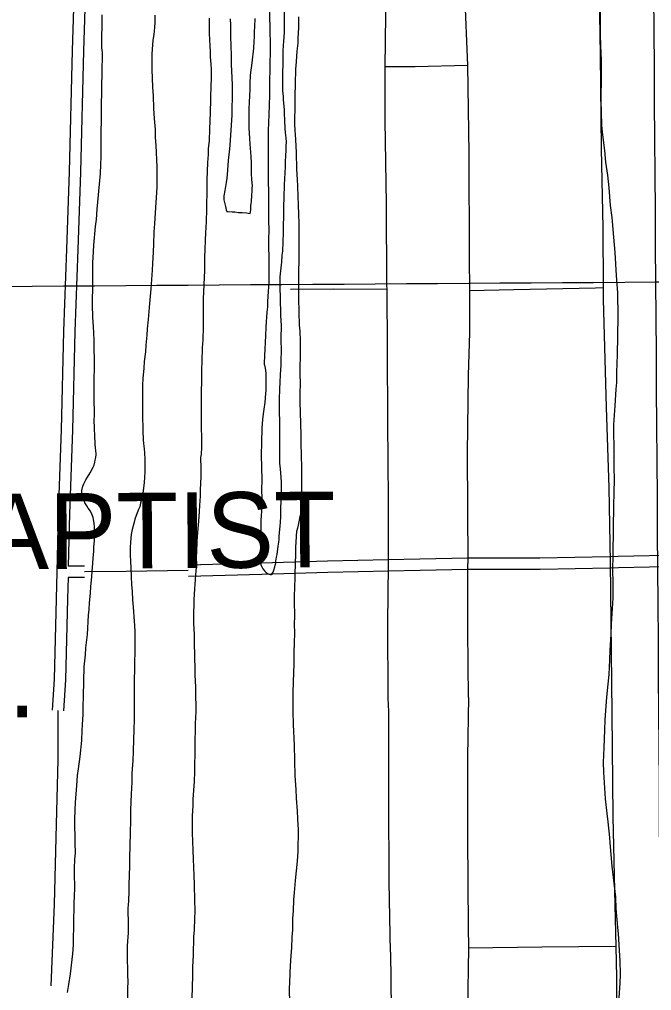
# Model space of a CAD drawing. Extents: x 3508733 to 3546731, y 546897 to 572481.
# Drawn here: x 3532290 to 3533961, y 556625 to 559192 of the extents above; entities that cross this region are included whole.
import ezdxf

# ---------------------------------------------------------------- set-up
doc = ezdxf.new("R2010")
doc.units = 0
for name, color, linetype in [('V-DTCH-CNTR', 7, 'Continuous'), ('V-GRID-MAJR', 7, 'Continuous'), ('V-ROAD-CNTR', 7, 'Continuous'), ('V-SITE-VEGE', 7, 'Continuous'), ('V-TOPO-GNAM-IDEN', 7, 'Continuous')]:
    doc.layers.add(name, color=color, linetype=linetype)

msp = doc.modelspace()

# ---------------------------------------------------------------- linework, layer by layer
at = {"layer": 'V-DTCH-CNTR'}
for points in [[(3533784.645, 560922.076), (3533790, 560756.678), (3533789.579, 560542.088), (3533793.89, 560331.554), (3533803.566, 560129.76), (3533804.558, 560115.881), (3533806.9990000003, 559952.27), (3533810.7490000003, 559744.087), (3533820.378, 559480.145), (3533821.472, 559298.958), (3533822.15, 559257.327), (3533824.722, 559099.575), (3533827.469, 558850.36), (3533831.79, 558640.9990000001), (3533832.6380000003, 558483.279), (3533832.804, 558452.192), (3533841.049, 558167.156), (3533847.68, 557954.254), (3533850.93, 557757.789), (3533853.8000000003, 557520.887), (3533855.661, 557357.868)], [(3533264.545, 557397.777), (3533264.224, 557597.527), (3533265.25, 557749.997), (3533265.235, 557922.133), (3533263.787, 558126.593), (3533262.819, 558320.475), (3533261.694, 558478.009), (3533261.606, 558490.273), (3533260.261, 558704.721), (3533256.617, 558924.479), (3533256.673, 559066.721), (3533259.454, 559273.074)], [(3533466.306, 559262.701), (3533474.1950000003, 559070.385), (3533477.83, 558838.67), (3533479.122, 558561.914), (3533479.274, 558475.7220000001), (3533479.466, 558364.904), (3533475.966, 558251.193), (3533473.296, 558046.008), (3533475.548, 557754.002)], [(3533474.1950000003, 559070.385), (3533335.789, 559067.1), (3533256.673, 559066.721)], [(3533479.274, 558475.7220000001), (3533596.5670000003, 558478.634), (3533812.373, 558482.306), (3533832.6380000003, 558483.279)], [(3533261.694, 558478.009), (3533120.399, 558478.857), (3533006.647, 558478.253)], [(3533476.64, 557400.327), (3533475.487, 557576.001), (3533475.548, 557754.002)], [(3533271.109, 556727.0700000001), (3533267.187, 556912.719), (3533266.681, 557132.856), (3533266.292, 557362.922), (3533264.545, 557397.777)], [(3533476.64, 557400.327), (3533474.199, 557243.336), (3533474.367, 557031.5970000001), (3533476.472, 556791.025), (3533477.1950000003, 556740.834)], [(3533855.661, 557357.868), (3533858.703, 557085.447), (3533863.8000000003, 556851.5430000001), (3533866.0840000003, 556741.647), (3533867.769, 556660.407), (3533870.198, 556391.23), (3533876.006, 556134.323), (3533881.515, 555879.687), (3533885.46, 555629.604), (3533889.8200000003, 555416.1140000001), (3533891.899, 555258.035)], [(3533477.1950000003, 556740.834), (3533477.1520000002, 556737.951), (3533474.653, 556575.102), (3533475.54, 556369.507), (3533474.092, 556129.623), (3533474.164, 555880.979), (3533474.881, 555746.987), (3533475.403, 555649.48), (3533479.204, 555359.028), (3533477.623, 555107.491), (3533479.21, 554793.106), (3533479.892, 554711.191)], [(3533866.0840000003, 556741.647), (3533670.903, 556739.8), (3533477.1520000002, 556737.951)], [(3533271.109, 556727.0700000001), (3533272.844, 556576.841), (3533272.166, 556404.194), (3533273.485, 556198.723), (3533274.078, 555948.584), (3533274.66, 555735.133)]]:
    msp.add_lwpolyline(points, dxfattribs=at)
at = {"layer": 'V-GRID-MAJR'}
for points in [[(3534014.4590000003, 552440.283), (3533972.165, 558498.1140000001), (3533929.85, 564559.029), (3533887.535, 570619.961), (3533887.514, 570623.028)], [(3512877.5640000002, 558356.976), (3518151.221, 558391.11), (3523424.875, 558426.011), (3528698.522, 558461.679), (3533972.165, 558498.1140000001), (3539245.802, 558535.316), (3544519.434, 558573.285), (3544519.435, 558573.285)]]:
    msp.add_spline(points, degree=3, dxfattribs=at)
at = {"layer": 'V-ROAD-CNTR'}
for p, q in [((3532462.4615447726, 557746.9739999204), (3532419.5511528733, 557746.9784190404)), ((3532462.4584552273, 557716.9740000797), (3532418.854686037, 557716.978490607))]:
    msp.add_line(p, q, dxfattribs=at)
for points in [[(3532465.2551178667, 560452.7004527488), (3532462.1440149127, 560319.9550598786), (3532456.8562898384, 560088.5490914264), (3532451.9148342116, 559891.2238296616), (3532445.1252728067, 559627.5666942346), (3532437.4320006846, 559390.8465513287), (3532435.104791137, 559277.4733429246), (3532429.8762249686, 559109.5503925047), (3532421.3386289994, 558789.4695399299), (3532414.56358583, 558585.1505532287), (3532407.0731313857, 558368.3715198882), (3532400.8995116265, 558107.6035808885), (3532392.774383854, 557886.1990991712), (3532389.2030406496, 557732.3281424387), (3532387.5506467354, 557661.1702426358), (3532381.8670998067, 557448.2484558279), (3532376.9424034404, 557366.8882848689)], [(3532495.2468821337, 560451.9975472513), (3532492.1359850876, 560319.2609401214), (3532486.847710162, 560087.8309085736), (3532481.9051657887, 559890.4621703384), (3532475.1127271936, 559626.6933057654), (3532467.4219993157, 559390.0514486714), (3532465.0952088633, 559276.6986570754), (3532459.8637750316, 559108.6836074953), (3532451.325371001, 558788.5724600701), (3532444.5464141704, 558584.1354467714), (3532437.0608686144, 558367.4984801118), (3532430.886488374, 558106.6984191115), (3532422.761616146, 557885.3009008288), (3532419.5480620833, 557746.8452526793)], [(3532735.8316419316, 557750.6496517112), (3532930.3391030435, 557756.3103741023), (3533104.349631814, 557761.5961823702), (3533264.932569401, 557764.9936408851), (3533348.3052498, 557766.7591847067), (3533474.7809253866, 557769.0017144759), (3533665.71604801, 557769.41170615), (3533850.6564458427, 557772.7865053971), (3533872.3767595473, 557773.1825083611), (3534036.993979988, 557777.387531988), (3534083.5773681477, 557777.7445619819), (3534195.506095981, 557778.5975006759), (3534437.487886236, 557784.9470577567), (3534687.262196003, 557791.2227941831), (3534940.667937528, 557796.8809143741), (3535048.7228697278, 557797.581533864)], [(3532736.7043580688, 557720.6623482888), (3532931.2308969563, 557726.3236258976), (3533105.1223681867, 557731.6058176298), (3533265.567430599, 557735.0003591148), (3533348.8887502, 557736.7648152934), (3533475.0790746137, 557739.0022855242), (3533666.02195199, 557739.41229385), (3533851.203554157, 557742.7914946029), (3533873.033240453, 557743.1894916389), (3534037.492020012, 557747.3904680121), (3534083.806631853, 557747.7454380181), (3534196.013904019, 557748.6004993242), (3534438.2581137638, 557754.9569422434), (3534687.973803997, 557761.231205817), (3534941.1000624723, 557766.883085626), (3535049.160988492, 557767.5837439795)], [(3532736.268, 557735.656), (3532572.333, 557733.209), (3532462.46, 557731.974)], [(3532418.8657245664, 557717.4538485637), (3532417.541353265, 557660.4217573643), (3532411.8429001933, 557446.941544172), (3532406.8875965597, 557365.075715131)], [(3532391.915, 557365.982), (3532392.0500000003, 557236.055), (3532387.165, 557064.066), (3532381.845, 556853.526), (3532373.54, 556637.5430000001)]]:
    msp.add_lwpolyline(points, dxfattribs=at)
at = {"layer": 'V-SITE-VEGE'}
for points in [[(3532995.127, 558879.389), (3532993.365, 558893.17), (3532992.515, 558902.781), (3532992.29, 558911.104), (3532991.737, 558918.792), (3532991.5470000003, 558929.995), (3532991.008, 558938.963), (3532990.539, 558954.01), (3532988.272, 558979.319), (3532987.739, 558988.926), (3532986.291, 559002.383), (3532986.0700000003, 559011.026), (3532986.582, 559055.826), (3532987.057, 559069.261), (3532987.526, 559110.221), (3532989.4020000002, 559134.52), (3532989.8370000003, 559144.435), (3532990.33, 559159.473), (3532991.082, 559225.39)], [(3532489.5530000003, 557834.341), (3532489.092, 557850.029), (3532487.937, 557860.924), (3532484.9080000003, 557876), (3532481.488, 557884.679), (3532478.056, 557892.4), (3532472.063, 557900.15), (3532468.612, 557906.269), (3532463.58, 557914.009), (3532462.028, 557917.867), (3532459.208, 557923.337), (3532457.6350000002, 557925.9180000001), (3532455.7630000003, 557930.1), (3532454.907, 557939.0700000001), (3532455.634, 557946.742), (3532458.0100000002, 557958.557), (3532460.963, 557964.924), (3532465.88, 557975.109), (3532476.97, 557993.5430000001), (3532485.467, 558008.806), (3532487.45, 558014.225), (3532489.453, 558021.563), (3532490.794, 558026.9890000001), (3532492.162, 558034.652), (3532492.887, 558042.007), (3532492.066, 558054.176), (3532491.466, 558057.704), (3532490.344, 558071.477), (3532490.112, 558079.161), (3532489.52, 558083.649), (3532488.642, 558118.542), (3532488.097, 558126.867), (3532488.382, 558151.831), (3532488.1750000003, 558189.596), (3532487.577, 558221.284), (3532488.378, 558291.363), (3532488.089, 558322.091), (3532488.0270000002, 558344.814), (3532486.194, 558380.357), (3532484.546, 558404.058), (3532483.657, 558438.313), (3532484.29, 558493.67), (3532484.22, 558515.754), (3532484.62, 558550.633), (3532485.068, 558561.83), (3532487.372, 558595.407), (3532491.771, 558644.321), (3532493.5840000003, 558662.862), (3532495.4990000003, 558690.362), (3532497.6350000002, 558709.22), (3532499.887, 558738.318), (3532501.7, 558756.857), (3532504.901, 558784.986), (3532506.382, 558830.4130000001), (3532505.96, 558849.621), (3532507.346, 558970.897), (3532508.276, 558996.17), (3532509.11, 559069.128), (3532509.595, 559083.523), (3532510.017, 559092.479), (3532510.06, 559096.319), (3532509.832, 559104.323), (3532508.37, 559116.5), (3532509.37, 559203.857)], [(3532647.941, 559203.554), (3532647.696, 559182.116), (3532647.2660000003, 559172.519), (3532646.487, 559160.366), (3532645.123, 559153.341), (3532642.6920000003, 559136.407), (3532642.238, 559124.571), (3532640.366, 559100.911), (3532639.899, 559059.951), (3532641.605, 559013.207), (3532643.901, 558990.138), (3532644.794, 558956.203)], [(3532950.988, 559217.53), (3532951.852, 559153.192), (3532952.631, 559137.181), (3532953.11, 559123.095), (3532952.362, 559057.817), (3532951.418, 559031.264), (3532950.9960000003, 558994.144), (3532950.3200000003, 558963.111), (3532949.452, 558943.278), (3532948.512, 558917.045), (3532947.687, 558900.733), (3532947.4220000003, 558877.6950000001), (3532947.883, 558862.007), (3532947.9450000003, 558839.285), (3532947.773, 558824.2440000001), (3532947.826, 558800.881), (3532947.468, 558769.522), (3532948.616, 558730.145), (3532948.745, 558713.503), (3532948.41, 558684.063), (3532948.4960000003, 558663.579), (3532949.102, 558632.529), (3532948.881, 558613.331), (3532949.659, 558541.313), (3532949.163, 558498.115), (3532947.13, 558460.052), (3532946.02, 558446.9450000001), (3532945.534, 558432.55), (3532944.414, 558418.48), (3532941.727, 558379.468), (3532940.49, 558355.158), (3532939.353, 558339.81), (3532938.477, 558319.019), (3532937.686, 558305.906), (3532937.406, 558281.2660000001), (3532937.688, 558278.063), (3532939.519, 558270.361)], [(3533027.954, 559198.612), (3533027.616, 559169.172), (3533026.838, 559157.022), (3533026.328, 559140.386), (3533025.879, 559129.189), (3533023.723, 559108.41), (3533022.605, 559094.662), (3533021.153, 559079.638), (3533019.973, 559060.448), (3533019.827, 559047.648), (3533019.361, 559034.852), (3533019.1410000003, 559015.654), (3533018.267, 558995.183), (3533018.435, 558981.737), (3533017.964, 558968.622), (3533017.741, 558949.103), (3533017.259, 558935.027), (3533017.341, 558914.223), (3533017.81, 558899.176), (3533019.772, 558874.832), (3533020.5300000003, 558857.221), (3533021.613, 558839.928), (3533022.715, 558796.389), (3533024.325, 558769.169), (3533025.079, 558751.2390000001), (3533025.718, 558723.069), (3533026.463, 558704.178), (3533027.4050000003, 558674.724), (3533028.458, 558654.871), (3533028.7630000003, 558625.422), (3533028.523, 558604.623), (3533028.484, 558573.262), (3533027.737, 558507.662), (3533027.682, 558475.019), (3533028.0870000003, 558454.533), (3533029.842, 558384.106), (3533030.94, 558368.091), (3533032.24, 558341.834), (3533032.349, 558323.2710000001), (3533032.034, 558295.752), (3533031.509, 558278.155), (3533031.532, 558251.912), (3533031.964, 558233.667), (3533031.577, 558199.748), (3533031.683, 558181.185), (3533032.955, 558124.525), (3533033.875, 558092.83), (3533033.955, 558072.026), (3533035.187, 558039.688), (3533035.466, 558008.006), (3533035.296, 557993.283), (3533035.982, 557969.274), (3533035.796, 557952.953), (3533036.5100000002, 557931.503), (3533036.6720000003, 557917.74), (3533036.218, 557905.905), (3533035.108, 557892.795), (3533035.069, 557889.275), (3533033.1010000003, 557885.138), (3533031.427, 557878.756), (3533029.713, 557868.854)], [(3533876.0160000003, 556731.063), (3533873.004, 556776.424), (3533871.419, 556792.337), (3533867.282, 556842.421), (3533865.858, 556872.459), (3533856.788, 556954.387), (3533851.602, 557015.6680000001), (3533849.9990000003, 557029.8150000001), (3533846.349, 557071.062), (3533843.072, 557093.469), (3533839.39, 557131.775), (3533836.7770000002, 557160.65), (3533834.313, 557202.474), (3533834.018, 557228.377), (3533835.044, 557266.63), (3533836.498, 557290.7490000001), (3533837.362, 557314.8740000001), (3533837.659, 557340.7710000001), (3533840.43, 557377.238), (3533842.464, 557400.761), (3533846.394, 557435.446), (3533848.448, 557460.735), (3533850.6580000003, 557499.5650000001), (3533851.543, 557525.454), (3533853.773, 557566.047), (3533854.684, 557594.291), (3533857.509, 557635.466), (3533859.012, 557663.704), (3533859.495, 557706.083), (3533858.647, 557734.936), (3533859.145, 557778.4940000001), (3533860.646, 557909.7490000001), (3533862.145, 557937.9890000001), (3533862.616, 557979.188), (3533861.73, 558004.512), (3533861.551, 558040.4230000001), (3533860.708, 558121.08), (3533864.812, 558171.069), (3533867.075, 558214.606), (3533869.049, 558232.831), (3533869.358, 558259.906), (3533871.06, 558305.803), (3533872.213, 558406.452), (3533871.755, 558469.4450000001), (3533868.1520000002, 558514.814), (3533864.142, 558576.08), (3533861.068, 558616.145), (3533856.37, 558668.588), (3533852.614, 558700.42), (3533849.026, 558746.965), (3533845.288, 558780.562), (3533839.793, 558814.768), (3533837.201, 558845.408), (3533831.786, 558886.678), (3533829.713, 558911.426), (3533828.357, 558947.35), (3533827.503, 558975.616), (3533828.304, 559045.658), (3533828.153, 559083.922), (3533826.832, 559122.789), (3533825.382, 559150.4720000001), (3533826.1890000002, 559221.104)], [(3532784.59, 558659.372), (3532785.233, 558687.528), (3532785.444, 558706.089), (3532786.3740000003, 558731.359), (3532786.788, 558767.519), (3532788.594, 558813.582), (3532789.798, 558835.011), (3532790.288, 558849.727), (3532792.147, 558872.428), (3532793.767, 558902.1730000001), (3532795.232, 558946.321), (3532795.311, 558953.36), (3532795.858, 558973.1950000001), (3532796.325, 558985.991), (3532796.677, 559016.711), (3532797.529, 559035.262), (3532797.804, 559059.262), (3532797.3310000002, 559073.67), (3532795.631, 559093.21), (3532795.133, 559105.701), (3532794.066, 559124.272), (3532793.2430000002, 559136.443), (3532792.846, 559157.571), (3532792.383, 559172.937), (3532792.313, 559195.02)], [(3532847.3370000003, 559193.112), (3532848.115, 559176.781), (3532847.98, 559165.261), (3532848.453, 559150.534), (3532848.346, 559141.254), (3532848.828, 559127.487), (3532848.7090000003, 559117.247), (3532849.504, 559102.5160000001), (3532850.007, 559090.669), (3532850.1040000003, 559071.147), (3532850.91, 559057.696), (3532851.625, 559036.245), (3532852.725, 559020.551), (3532852.85, 559003.268), (3532852.643, 558985.348), (3532852.002, 558957.194), (3532851.47, 558938.637), (3532849.569, 558912.417), (3532846.88, 558873.083), (3532846.403, 558859.326), (3532844.912, 558840.782), (3532843.161, 558827.681), (3532841.33, 558807.539), (3532840.197, 558792.51), (3532838.051, 558772.692), (3532836.636, 558760.8690000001), (3532834.592, 558750.01), (3532832.88, 558740.108), (3532830.7970000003, 558726.051), (3532830.4020000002, 558719.335), (3532830.3510000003, 558714.854), (3532830.949, 558711.328), (3532834.633, 558697.846), (3532836.773, 558688.859), (3532838.3170000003, 558684.04), (3532841.518, 558684.005), (3532852.072, 558683.2440000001), (3532859.75, 558683.155), (3532869.338, 558682.086), (3532871.898, 558682.058), (3532879.255, 558681.652), (3532890.1240000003, 558680.569), (3532894.92, 558680.194), (3532900.349, 558679.172), (3532901.418, 558688.761), (3532901.525, 558698.04), (3532902.901, 558706.345), (3532903.579, 558709.857), (3532903.948, 558714.015), (3532904.056, 558723.6140000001), (3532904.447, 558729.6900000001), (3532905.166, 558736.723), (3532905.512, 558738.959), (3532905.606, 558747.278), (3532906.2970000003, 558751.43), (3532904.589, 558770.013), (3532903.788, 558784.103), (3532903.681, 558802.666), (3532903.804, 558813.545), (3532903.026, 558829.237), (3532902.196, 558840.767), (3532900.198, 558861.911), (3532899.102, 558877.926), (3532897.482, 558904.188), (3532897.361, 558921.79), (3532897.728, 558953.79), (3532898.293, 558975.227), (3532899.088, 558988.658), (3532899.6410000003, 559009.134), (3532899.794, 559022.575), (3532901.33, 559044.957), (3532904.9, 559077.242), (3532909.506, 559116.232), (3532910.663, 559133.5), (3532911.126, 559145.977), (3532911.916, 559159.088), (3532912.074, 559172.849), (3532912.963, 559194.6)], [(3532644.794, 558956.203), (3532646.092, 558929.948), (3532648.64, 558900.794), (3532649.369, 558880.6240000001), (3532650.725, 558859.167), (3532653.276, 558802.49), (3532653.661, 558780.085), (3532653.299, 558748.405), (3532649.328, 558681.245), (3532647.071, 558651.508), (3532645.877, 558631.0380000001), (3532644.869, 558599.046), (3532643.661, 558577.2980000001), (3532642.3540000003, 558546.91), (3532641.187, 558528.998), (3532637.429, 558480.08), (3532634.5330000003, 558450.669), (3532633.784, 558441.078), (3532630.1010000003, 558398.875), (3532628.219, 558374.254), (3532627.068, 558357.626), (3532624.523, 558330.77), (3532623.04, 558313.186), (3532620.191, 558287.937), (3532618.714, 558270.672), (3532616.1580000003, 558243.177), (3532615.6380000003, 558225.581), (3532615.1180000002, 558180.142), (3532615.661, 558171.495), (3532615.8140000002, 558157.094), (3532615.526, 558131.813), (3532616.052, 558121.887), (3532616.1750000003, 558104.604), (3532617.185, 558080.908), (3532618.0300000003, 558070.978), (3532619.79, 558056.877), (3532620.633, 558046.627), (3532621.715, 558029.331), (3532621.883, 558015.888), (3532621.651, 557995.73), (3532621.1920000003, 557983.573), (3532620.363, 557966.943), (3532616.535, 557940.104), (3532614.807, 557928.922), (3532610.467, 557913.2880000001), (3532608.116, 557903.713), (3532604.176, 557894.7980000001), (3532594.941, 557870.9), (3532592.258, 557860.052), (3532587.91, 557843.779), (3532585.52, 557830.686), (3532584.0130000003, 557810.859), (3532583.2060000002, 557796.148), (3532582.969, 557775.349), (3532583.444, 557760.939), (3532585.223, 557720.598), (3532586.559, 557697.539), (3532587.974, 557681.202), (3532589.295, 557656.8640000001), (3532589.85, 557649.497), (3532591.838, 557627.3910000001), (3532592.957, 557613.297), (3532594.614, 557590.236), (3532595.062, 557573.59), (3532595.386, 557545.743), (3532595.136, 557523.983), (3532594.093, 557488.7930000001), (3532593.454, 557432.792), (3532593.85, 557411.345), (3532593.85, 557383.501), (3532593.399, 557344.144), (3532592.717, 557312.468), (3532591.832, 557291.0380000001), (3532590.802, 557256.805), (3532589.571, 557233.137), (3532587.2630000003, 557199.242), (3532587.003, 557176.52), (3532585.682, 557144.851), (3532584.484, 557124.064), (3532584.23, 557101.985), (3532583.544, 557069.9890000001), (3532582.981, 557048.552), (3532582.446, 557001.833), (3532581.59, 556982.961), (3532581.259, 556953.843), (3532579.745, 556905.534), (3532579.544, 556887.936), (3532578.615, 556862.664), (3532577.84, 556850.83), (3532576.808, 556844.443), (3532576.694, 556834.522), (3532576.911, 556825.56), (3532577.4450000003, 556816.272), (3532577.339, 556806.993), (3532577.472, 556790.67), (3532577.322, 556777.547), (3532575.805, 556756.7660000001), (3532575.313, 556741.729), (3532575.059, 556719.65), (3532575.213, 556704.927), (3532575.9280000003, 556683.476)], [(3532939.519, 558270.361), (3532941.287, 558256.899), (3532941.696, 558236.732), (3532941.403, 558211.134), (3532940.9960000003, 558203.459), (3532938.485, 558179.804), (3532936.04, 558161.911), (3532934.625, 558150.086), (3532932.529, 558134.746), (3532931.307, 558111.718), (3532931.186, 558101.159), (3532930.039, 558084.851), (3532929.4080000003, 558029.813), (3532929.924, 558018.926), (3532930.094, 558005.802), (3532930.7290000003, 557977.31), (3532930.381, 557946.912), (3532930.49, 557928.349), (3532930.086, 557893.15), (3532929.289, 557879.397), (3532928.538, 557869.805), (3532928.36, 557854.125), (3532927.915, 557842.931), (3532927.291, 557788.532), (3532927.454, 557774.767), (3532928.282, 557763.2390000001), (3532928.466, 557751.393), (3532929.0810000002, 557749.147), (3532933.779, 557740.131), (3532937.877, 557734.645), (3532941.041, 557731.409), (3532946.116, 557727.51), (3532953.126, 557724.87), (3532956.651, 557725.148), (3532960.88, 557731.182), (3532962.86, 557736.599), (3532965.203, 557745.534), (3532966.534, 557749.9990000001), (3532967.556, 557755.428), (3532967.927, 557759.905), (3532969.969, 557770.442), (3532971.017, 557778.109), (3532974.468, 557800.152), (3532975.861, 557810.058), (3532976.267, 557817.415), (3532977.0100000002, 557826.3690000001), (3532977.4420000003, 557836.283), (3532979.23, 557852.585), (3532979.99, 557863.134), (3532980.799, 557877.849), (3532981.231, 557887.7660000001), (3532981.413, 557903.764), (3532982.181, 557914.957), (3532982.808, 557969.675), (3532980.006, 558004.5920000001), (3532978.575, 558019.329), (3532978.171, 558040.137), (3532978.714, 558087.495), (3532978.286, 558106.062), (3532978.415, 558117.26), (3532978.302, 558135.504), (3532977.8170000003, 558148.951), (3532977.665, 558163.674), (3532977.946, 558188.314), (3532978.566, 558214.5480000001), (3532979.427, 558233.74), (3532979.957, 558252.297), (3532981.5300000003, 558277.883), (3532982.3680000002, 558295.154), (3532982.5640000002, 558312.435), (3532982.034, 558349.884), (3532982.4020000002, 558382.204), (3532981.622, 558397.572), (3532981.427, 558408.777), (3532980.676, 558427.026), (3532980.5100000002, 558440.47), (3532979.8030000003, 558462.561), (3532979.0130000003, 558477.61), (3532979.302, 558502.89), (3532979.721, 558511.527), (3532982.963, 558543.1730000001), (3532983.367, 558550.531), (3532984.86, 558569.074), (3532985.943, 558579.942), (3532988.4280000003, 558629.201), (3532989.116, 558689.359), (3532988.862, 558695.122), (3532988.899, 558698.319), (3532990.109, 558720.39), (3532990.224, 558730.311), (3532990.725, 558746.306), (3532991.162, 558756.541), (3532991.9420000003, 558768.694), (3532992.485, 558788.21), (3532993.5840000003, 558800.358), (3532993.791, 558818.598), (3532994.5670000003, 558830.429), (3532995.086, 558847.706), (3532995.522, 558857.942), (3532995.632, 558867.541), (3532995.127, 558879.389)], [(3532746.379, 556604.556), (3532748.67, 556665.015), (3532748.932, 556687.736), (3532750.255, 556719.724), (3532751.441, 556767.395), (3532752.617, 556786.263), (3532753.913, 556815.693), (3532754.4560000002, 556835.208), (3532754.165, 556865.615), (3532752.6780000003, 556903.716), (3532751.714, 556931.2490000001), (3532750.9560000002, 556948.86), (3532750.616, 556975.105), (3532749.551, 556994), (3532748.273, 557022.178), (3532747.8310000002, 557039.465), (3532747.7630000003, 557061.547), (3532748.0700000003, 557088.429), (3532748.523, 557099.943), (3532749.33, 557114.656), (3532749.836, 557130.97), (3532752.615, 557177.984), (3532753.878, 557204.532), (3532755.322, 557330.927), (3532756.969, 557362.914), (3532757.1, 557374.434), (3532756.197, 557407.407), (3532756.438, 557428.526), (3532754.861, 557458.628), (3532754.7630000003, 557477.832), (3532753.788, 557504.726), (3532752.701, 557549.544), (3532752.586, 557567.466), (3532751.613, 557594.359), (3532751.171, 557611.6460000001), (3532751.701, 557658.045), (3532753.639, 557687.4670000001), (3532756.623, 557724.554), (3532757.794, 557743.103), (3532758.423, 557769.981), (3532759.252, 557786.613), (3532759.85, 557810.927), (3532761.304, 557826.272), (3532764.643, 557866.2390000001), (3532766.207, 557891.184), (3532766.713, 557907.498), (3532768.591, 557931.8), (3532769.091, 557947.155), (3532769.326, 557967.957), (3532770.438, 557981.384), (3532770.352, 558001.868), (3532770.49, 558014.027), (3532769.988, 558025.8740000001), (3532769.7630000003, 558034.198), (3532771.778, 558042.496), (3532772.636, 558061.688), (3532772.646, 558090.491), (3532771.589, 558110.025), (3532771.294, 558140.431), (3532771.219, 558161.554), (3532771.464, 558182.993), (3532771.481, 558212.437), (3532772.032, 558232.591), (3532772.73, 558265.867), (3532773.637, 558289.219), (3532774.035, 558323.779), (3532775.563, 558345.522), (3532776.9, 558378.47), (3532776.509, 558400.2390000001), (3532776.5500000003, 558431.921), (3532777.119, 558453.677), (3532780.214, 558528.21), (3532780.611, 558563.087), (3532783.294, 558629.944), (3532784.056, 558640.5), (3532784.59, 558659.372)], [(3533029.713, 557868.854), (3533028.011, 557859.9130000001), (3533024.984, 557847.145), (3533022.646, 557838.532), (3533021.562, 557827.6630000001), (3533020.3910000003, 557809.1140000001), (3533019.9560000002, 557799.198), (3533019.66, 557773.278), (3533019.1720000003, 557758.563), (3533019.051, 557748.004), (3533018.218, 557731.05), (3533017.751, 557718.255), (3533017.4250000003, 557689.775), (3533016.549, 557668.984), (3533016.372, 557653.6240000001), (3533016.911, 557616.813), (3533016.626, 557591.854), (3533017.0500000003, 557572.9670000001), (3533016.698, 557542.2490000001), (3533015.49, 557520.502), (3533015.113, 557487.541), (3533014.236, 557466.75), (3533012.985, 557413.318), (3533012.875, 557375.555), (3533012.741, 557364.037), (3533013.616, 557328.502), (3533016.19, 557273.746), (3533018.464, 557192.752), (3533020.294, 557156.888), (3533021.31, 557133.833), (3533023.811, 557100.522), (3533025.173, 557079.705), (3533026.443, 557050.568), (3533025.789, 556993.609), (3533023.889, 556967.384), (3533018.824, 556916.2390000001), (3533015.901, 556884.59), (3533014.718, 556865.08), (3533013.43, 556836.296), (3533012.236, 556815.826), (3533011.578, 556786.39), (3533010.394, 556766.881), (3533009.106, 556738.0920000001), (3533007.918, 556718.263), (3533005.369, 556691.09), (3533004.517, 556672.5380000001), (3533003.544, 556643.425), (3533003.437, 556634.1460000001), (3533003.865, 556587.736)], [(3532417.107, 556620.324), (3532420.865, 556641.084), (3532425.355, 556669.834), (3532431.716, 556722.2490000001), (3532433.268, 556746.233), (3532433.4560000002, 556762.551), (3532434.474, 556795.504), (3532435.22, 556860.782), (3532435.969, 556870.3740000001), (3532436.315, 556900.775), (3532436.711, 556907.171), (3532436.449, 556912.295), (3532435.586, 556920.944), (3532435.898, 556948.143), (3532436.4960000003, 556972.459), (3532438.281, 556988.761), (3532437.95, 557015.647), (3532437.188, 557032.938), (3532436.8540000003, 557059.825), (3532437.059, 557077.745), (3532437.9930000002, 557103.336), (3532438.8510000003, 557122.528), (3532441.603, 557167.302), (3532444.149, 557194.155), (3532446.269, 557211.411), (3532450.481, 557244.007), (3532454.805, 557286.202), (3532456.0640000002, 557312.431), (3532456.566, 557328.426), (3532458.794, 557355.283), (3532459.009, 557374.164), (3532459.6750000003, 557404.2390000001), (3532461.836, 557481.3420000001), (3532465.0670000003, 557512.349), (3532466.247, 557531.2170000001), (3532469.843, 557566.06), (3532472.9930000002, 557617.5480000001), (3532474.449, 557632.894), (3532475.9220000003, 557649.839), (3532477.8140000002, 557675.421), (3532479.2970000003, 557693.005), (3532481.509, 557718.582), (3532482.957, 557733.287), (3532484.48, 557754.711), (3532485.592, 557767.8200000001), (3532486.768, 557786.689), (3532487.223, 557798.526), (3532488.683, 557814.189), (3532488.791, 557823.79), (3532489.5530000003, 557834.341)], [(3533875.179, 556606.277), (3533877.389, 556645.103), (3533878.253, 556669.228), (3533878.06, 556703.96), (3533876.0160000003, 556731.063)], [(3532575.9280000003, 556683.476), (3532576.077, 556668.753), (3532576.47, 556646.987), (3532575.6720000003, 556633.232), (3532574.875, 556563.475)]]:
    msp.add_lwpolyline(points, dxfattribs=at)

# ---------------------------------------------------------------- texts
at = {"layer": 'V-TOPO-GNAM-IDEN'}
for s, height, rotation, p in [('BAPTIST', 199.99959800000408, 0.357991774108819, (3532011.984238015, 557737.3036721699)), ('LA.', 199.99959800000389, 0.36571277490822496, (3531933.1030280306, 557345.2473989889))]:
    msp.add_text(s, height=height, rotation=rotation, dxfattribs=at).set_placement(p)

doc.saveas('drawing.dxf')
